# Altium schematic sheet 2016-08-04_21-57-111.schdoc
size 344 x 212 mm; SheetNumber: 1; SheetTotal: 1
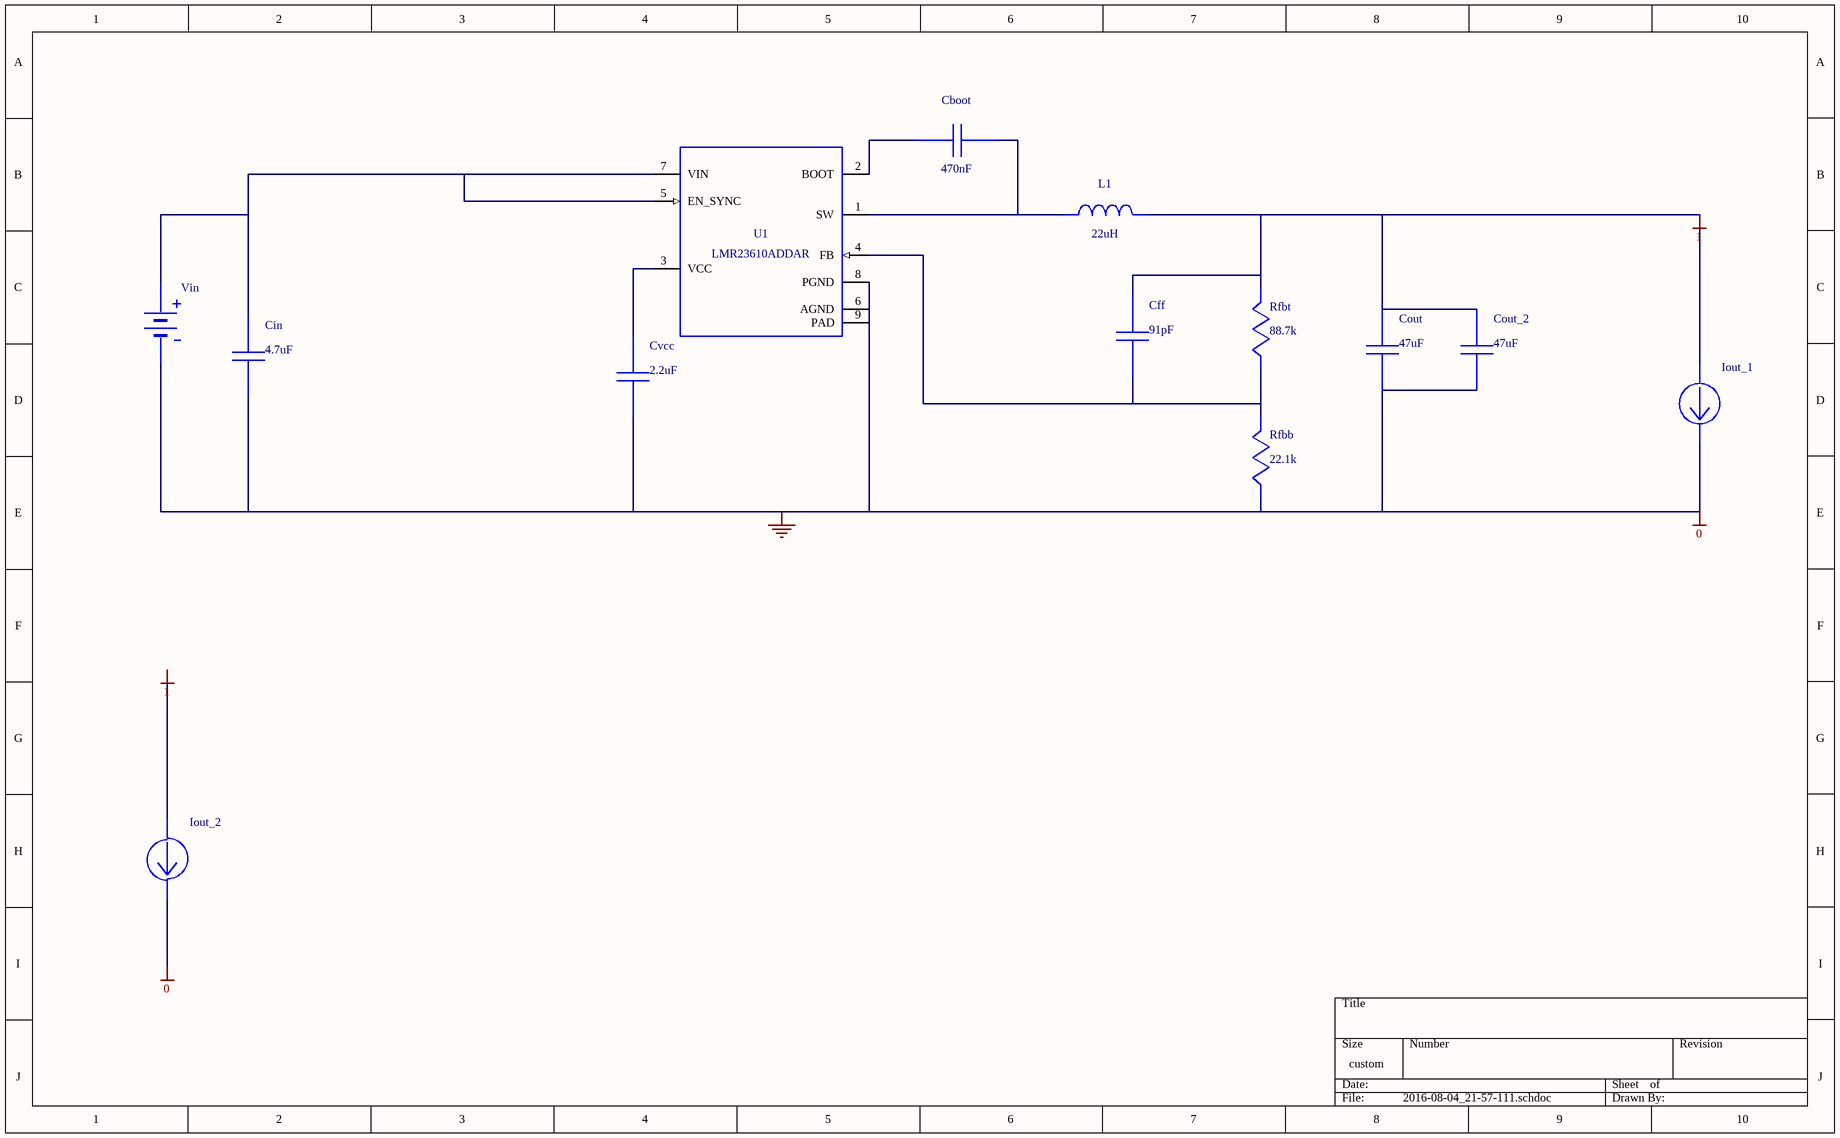
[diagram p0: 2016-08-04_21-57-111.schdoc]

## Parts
Cboot  value 470nF  (hidden comment: UMK212B7474KG-T)
Cff  value 91pF  (hidden comment: CL21C910JBANNNC)
Cin  value 4.7uF  (hidden comment: GRM32ER71H475KA88L)
Cout  value 47uF  (hidden comment: GRM31CR61A476KE15L)
Cout_2  value 47uF  (hidden comment: GRM31CR61A476KE15L)
Cvcc  value 2.2uF  (hidden comment: GRM188R60J225KE19D)
Iout_1  WB_CURRENT_LOAD  (value not drawn)
Iout_2  WB_CURRENT_LOAD  (value not drawn)
L1  value 22uH  (hidden comment: SRN6045-220M)
Rfbb  value 22.1k  (hidden comment: ERJ-6ENF2212V)
Rfbt  value 88.7k  (hidden comment: ERJ-6ENF8872V)
U1  LMR23610ADDAR
Vin  WB_BATTERY  (value not drawn)

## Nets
0: Cin.2 Cout.2 Cout_2.2 Cvcc.2 Iout_1.2(-) Iout_2.2(-) Rfbb.2 U1.6(AGND) U1.8(PGND) U1.9(PAD) Vin.2(-)
1: Cff.1 Cout.1 Cout_2.1 Iout_1.1(+) Iout_2.1(+) L1.2 Rfbt.1
NetCboot_1: Cboot.1 U1.2(BOOT)
NetCboot_2: Cboot.2 L1.1 U1.1(SW)
NetCff_2: Cff.2 Rfbb.1 Rfbt.2 U1.4(FB)
NetCin_1: Cin.1 U1.5(EN_SYNC) U1.7(VIN) Vin.1(+)
NetCvcc_1: Cvcc.1 U1.3(VCC)

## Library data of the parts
Cboot = UMK212B7474KG-T: Manufacturer Name: Taiyo Yuden
Cff = CL21C910JBANNNC: Manufacturer Name: Samsung Electro-Mechanics
Cin = GRM32ER71H475KA88L: GRM32ER71H475KA8; Manufacturer Name: MuRata
Cout Cout_2 = GRM31CR61A476KE15L: GRM31CR61A476KE1; Manufacturer Name: MuRata
Cvcc = GRM188R60J225KE19D: GRM188R60J225KE1; Manufacturer Name: MuRata
L1 = SRN6045-220M: Manufacturer Name: Bourns
Rfbb = ERJ-6ENF2212V: Manufacturer Name: Panasonic
Rfbt = ERJ-6ENF8872V: Manufacturer Name: Panasonic
U1 = LMR23610ADDAR: Manufacturer Name: Texas Instruments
